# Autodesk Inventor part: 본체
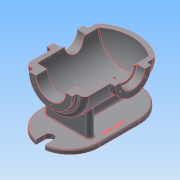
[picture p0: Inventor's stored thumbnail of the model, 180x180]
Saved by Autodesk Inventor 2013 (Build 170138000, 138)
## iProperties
Created: 2016-02
Part Number: 본체
Material: 알루미늄 6061
Document SubType Name: Modeling
Designer: mduedu
Density: 2.71 g/cm^3
Mass: 2164.61 g
Surface Area: 1516.74 cm^2
Volume: 798.749 cm^3
Author: mduedu
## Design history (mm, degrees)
sketch "스케치2"
  geometry: L1 (0, 90)-(0, -90); L2 (65, -65.993)-(65, 90); L3 (65, 90)-(0, 90); A1 r 100 centre (0, 10) between (0, -90) and (65, -65.993); 2 further points
  constraints: 6 end point, 2 point on circle, 1 centre point, 1 coincident, 1 horizontal, 1 midpoint, 1 parallel, 1 point on line, 1 vertical
  dimensions: "d3" = 180 distance of L1.start L1.end; "d5" = 130 diameter of L2 L1; "d6" = 100 radius of A1
revolve "회전1" sketch "스케치2" stored, may be unused: angle "d7" = 90 deg
sketch "스케치3"
  geometry: C1 r 47.5 at (0, 0); 1 further point
  constraints: 1 centre point, 1 coincident
  dimensions: "d8" = 95 diameter of C1
extrude "돌출2" join sketch "스케치3" distance "d10" = 10; taper "d11" = 0 deg
sketch "스케치5"
  geometry: L1 (47.5, 100)-(47.5, 90) reference; L2 (47.5, 90)-(65, 90) reference; L3 (65, 90)-(65, -65.993) reference; L4 (-65, -65.993)-(-65, 90) reference; L5 (-65, 90)-(-47.5, 90) reference; L6 (-47.5, 90)-(-47.5, 100) reference; L7 (-47.5, 100)-(47.5, 100) reference; L8 (55, 75)-(55, -61.239); L9 (0, 75)-(55, 75); L10 (0, 75)-(0, -80); A1 r 100 centre (0, 10) between (-65, -65.993) and (0, -90) reference; A2 r 100 centre (0, 10) between (0, -90) and (65, -65.993) reference; A3 r 90 centre (0, 10) between (0, -80) and (55, -61.239); 1 further point
  constraints: 6 end point, 2 point on circle, 1 centre point, 1 parallel, 1 perpendicular, 1 point on line, 1 vertical
  dimensions: "d13" = 10 distance between parallel lines of L3 L8; "d14" = 10 radial gap between concentric circles of A3 A1; "d15" = 15 distance between parallel lines of L9 L2
revolve "회전2" sketch "스케치5" stored, may be unused: angle "d16" = 90 deg
hole "구멍1" diameter "d19" = 65; stored, may be unused: countersink angle "d23" = 90 deg, drill point angle "d25" = 118 deg; dims "d17" = 10, "d18" = 10, "d20" = 6, "d21" = 4, "d22" = 2, "d24" = 8
node "작업 평면1"
sketch "스케치6"
  geometry: L1 (47.5, 100)-(-47.5, 100) reference; C1 r 40 at (0, -7); 1 further point
  constraints: 1 centre point, 1 vertical alignment
  dimensions: "d27" = 80 diameter of C1; "d29" = 107 distance from line of C1.centre L1
extrude "돌출3" join sketch "스케치6" stored distance "d30" = 10; taper "d31" = 0 deg
hole "구멍2" diameter "d34" = 42; stored, may be unused: countersink angle "d38" = 90 deg, drill point angle "d40" = 118 deg; dims "d32" = 10, "d33" = 10, "d35" = 6, "d36" = 52, "d37" = 18, "d39" = 8
sketch "스케치7" dims "d41" = 65
  geometry: C1 r 40 at (0, 0) reference; 3 further points
  constraints: 2 vertical alignment, 1 coincident, 2 other
hole "구멍3" sketch "스케치7" at (0, 32.5) diameter "d43" = 3.242; stored, may be unused: countersink angle "d47" = 90 deg, drill point angle "d49" = 118 deg; dims "d44" = 11, "d45" = 13, "d46" = 18, "d48" = 13
sketch "스케치8" dims "d53" = 80
  geometry: 3 further points
  constraints: 2 vertical alignment, 1 coincident, 2 other
hole "구멍4" sketch "스케치8" at (0, -40) diameter "d56" = 3.242; stored, may be unused: countersink angle "d60" = 90 deg, drill point angle "d62" = 118 deg; dims "d57" = 11, "d58" = 13, "d59" = 18, "d61" = 13
fillet "모깎기1" dims "d66" = 10
fillet "모깎기2" dims "d67" = 3
fillet "모깎기3" dims "d68" = 0.3
chamfer "모따기1" distance "d69" = 1; stored, may be unused: second distance "d70" = 2, angle "d71" = 45 deg
node "작업 평면5"
sketch "스케치10"
  geometry: L1 (-50, 66)-(50, 66); L2 (50, 66)-(50, 50); L3 (50, 50)-(-50, 50); L4 (-50, 50)-(-50, 66); 2 further points
  constraints: 8 end point, 2 horizontal, 2 vertical, 1 midpoint, 1 vertical alignment
  dimensions: "d177" = 50 distance from line of L3 point (0, 0); "d178" = 100 distance of L1.start L1.end; "d179" = 16 distance of L3.end L1.start
extrude "돌출5" join sketch "스케치10" stored distance "d84" = 10; taper "d85" = 0 deg
sketch "스케치21" dims "d180" = 220, "d182" = 130
  geometry: L1 (65, 58)-(-65, 58); L2 (-65, 58)-(-65, -32); L3 (-65, -32)-(65, -32); L4 (65, -32)-(65, 58); L5 (50, 50)-(50, 66) reference; 4 further points
  constraints: 8 end point, 3 horizontal alignment, 3 midpoint, 2 parallel, 1 horizontal, 1 perpendicular, 1 vertical alignment, 4 other
extrude "돌출13" join sketch "스케치21" distance "d183" = 10; taper "d184" = 0 deg
sketch "스케치11"
  geometry: L1 (-65, 80)-(-65, -61.239) reference; L2 (-100, -97)-(-100, -32) reference; L3 (-65, -42.793)-(-100, -63); L4 (-100, -97)-(-110, -97) reference; 1 further point
  constraints: 2 end point, 2 point on line
  dimensions: "d185" = 34 distance from line of L3.end L4; "d186" = 120 deg angle of L2 L3
feature "리브1" sketch "스케치11" dims "d88" = 1, "d89" = 16, "d90" = 0, "d91" = 0, "d92" = 1, "d93" = 1
fillet "모깎기12"
fillet "모깎기13"
fillet "모깎기16" dims "d167" = 3
fillet "모깎기18"
fillet "모깎기17" dims "d168" = 3
fillet "모깎기19" dims "d187" = 3
node "작업 평면6"
sketch "스케치19"
  geometry: L1 (75, -47)-(75, 33) reference; L2 (-75, -47)-(-75, 33) reference; L3 (75, -7)-(-75, -7); C1 r 22.5 at (0, -7); 1 further point
  constraints: 3 midpoint, 2 end point, 1 centre point
  dimensions: "d149" = 45 diameter of C1
extrude "돌출11" join sketch "스케치19" stored distance "d150" = 10; taper "d151" = 0 deg
hole "구멍6" diameter "d154" = 33.376; stored, may be unused: countersink angle "d158" = 90 deg, drill point angle "d160" = 118 deg; dims "d155" = 6, "d156" = 4, "d157" = 2, "d159" = 8, "d190" = 10, "d191" = 10
fillet "모깎기11" dims "d161" = 3
chamfer "모따기3" distance "d164" = 1; stored, may be unused: second distance "d165" = 2, angle "d166" = 45 deg
node "작업 평면9"
  node "작업 평면8"
sketch "스케치22" dims "d189" = 20
  geometry: L1 (-10, -123)-(10, -123); L2 (10, -123)-(10, -103); L3 (10, -103)-(-10, -103); L4 (-10, -103)-(-10, -123); A1 r 65 centre (0, -58) between (-65, -58) and (65, -58) reference; 2 further points
  constraints: 8 end point, 2 parallel, 1 horizontal, 1 horizontal alignment, 1 midpoint, 1 perpendicular, 1 tangent, 1 vertical alignment, 2 other
  dimensions: "d193" = 30 dimension on L1
extrude "돌출14" cut sketch "스케치22" stored distance "d194" = 10; taper "d195" = 0 deg
fillet "모깎기21" dims "d196" = 3
feature "분할1"
sketch "스케치23"
  geometry: L1 (-65, 32)-(-65, -58) reference; L2 (65, -58)-(65, 32) reference; L3 (-65, -13)-(65, -13); 2 further points
  constraints: 2 end point, 2 midpoint, 1 point on line, 1 other
  dimensions: "d197" = 12 distance from line of point (53, -13) L2
feature "엠보싱2" sketch "스케치23" dims "d8" = 95, "d198" = 0.5, "d199" = 0
node "솔리드2"
pattern_circular "원형 패턴1" dims angle "d51" = 360 deg
mirror "대칭1"
pattern_circular "원형 패턴2" dims angle "d64" = 360 deg
mirror "대칭3"
node "절단 모서리 투영1"
other parameters: "d26" = 75, "d136" = 175
